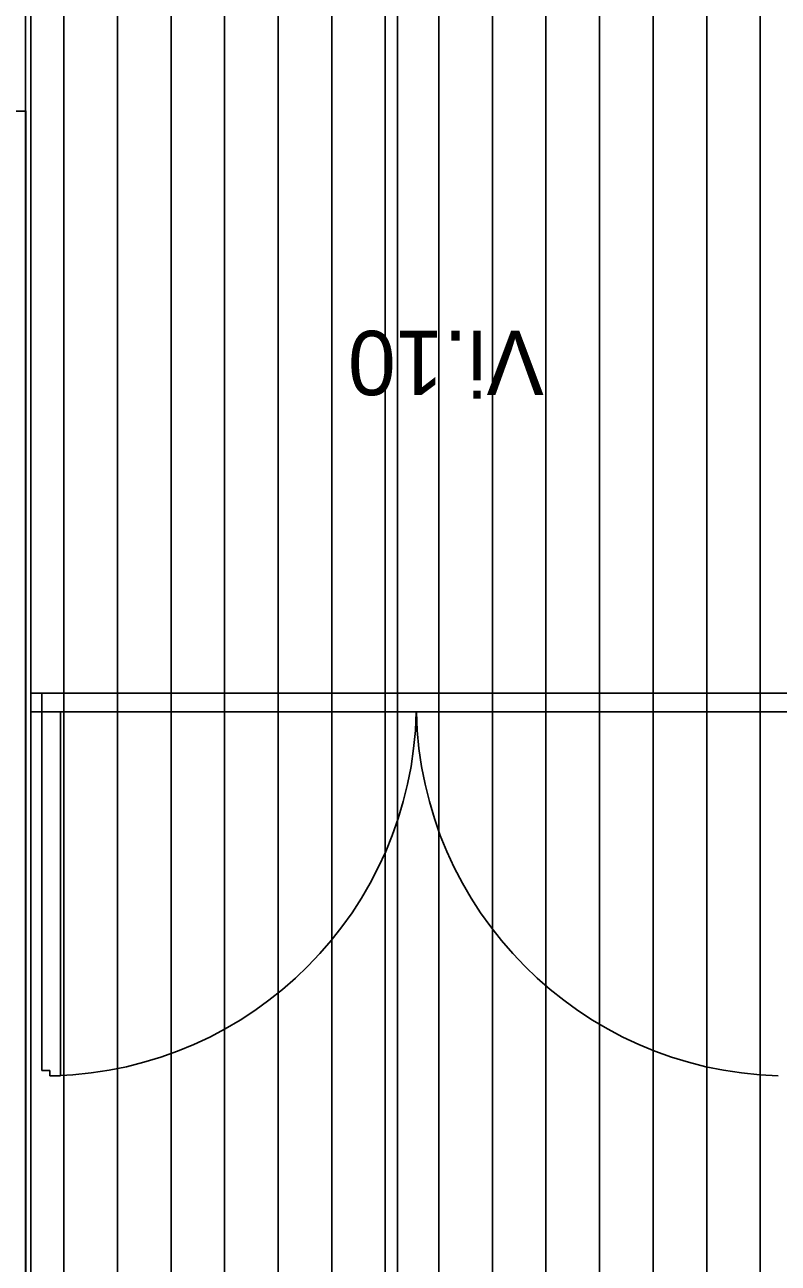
# Model space of a CAD drawing. Extents: x 1278 to 1356, y -253.7 to -224.
# Drawn here: x 1303.561 to 1304.967, y -239.071 to -236.76 of the extents above; entities that cross this region are included whole.
import ezdxf

# ---------------------------------------------------------------- set-up
doc = ezdxf.new("R2010")
doc.units = 0
for name, color, linetype in [('Level 10', 7, 'Continuous'), ('Level 13', 7, 'Continuous'), ('Level 4', 7, 'Continuous'), ('Level 40', 7, 'Continuous'), ('Level 65', 7, 'Continuous'), ('Level 66', 7, 'Continuous'), ('Level 67', 7, 'Continuous'), ('Level 93', 7, 'Continuous')]:
    doc.layers.add(name, color=color, linetype=linetype)

msp = doc.modelspace()

# ---------------------------------------------------------------- linework, layer by layer
at = {"layer": 'Level 10'}
for p, q in [((1303.6337, -243.574), (1303.6337, -235.1552)), ((1303.7337, -243.574), (1303.7337, -235.1552)), ((1303.8337, -243.574), (1303.8337, -235.1552)), ((1303.9337, -243.574), (1303.9337, -235.1552)), ((1304.0337, -243.574), (1304.0337, -235.1552)), ((1304.1337, -243.574), (1304.1337, -235.1552)), ((1304.2337, -243.574), (1304.2337, -235.1552)), ((1304.3337, -243.574), (1304.3337, -235.1552)), ((1304.4337, -243.574), (1304.4337, -235.1552)), ((1304.5337, -243.574), (1304.5337, -235.1552)), ((1304.6337, -243.574), (1304.6337, -235.1552)), ((1304.7337, -243.574), (1304.7337, -235.1552)), ((1304.8337, -243.574), (1304.8337, -235.1552)), ((1304.9337, -243.574), (1304.9337, -235.1552))]:
    msp.add_line(p, q, dxfattribs=at)
at = {"layer": 'Level 13'}
for p, q in [((1303.5923, -238.0075), (1303.5723, -238.0075)), ((1303.5923, -238.0075), (1303.5723, -238.0075)), ((1303.5923, -238.0075), (1303.5723, -238.0075)), ((1303.5923, -238.0425), (1303.5923, -238.0075)), ((1303.5923, -238.0425), (1303.5923, -238.0075)), ((1303.5923, -238.0425), (1303.5923, -238.0075)), ((1303.5923, -238.0425), (1303.5723, -238.0425)), ((1303.5923, -238.0425), (1303.5723, -238.0425)), ((1303.5923, -238.0425), (1303.5723, -238.0425)), ((1303.5923, -238.0425), (1303.5923, -238.7116)), ((1303.5923, -238.0425), (1303.5923, -238.7116)), ((1303.5923, -238.0425), (1303.5923, -238.7116)), ((1303.6273, -238.0425), (1303.5923, -238.0425)), ((1303.6273, -238.0425), (1303.5923, -238.0425)), ((1303.6273, -238.0425), (1303.5923, -238.0425)), ((1303.6273, -238.0425), (1303.6273, -238.7216)), ((1303.6273, -238.0425), (1303.6273, -238.7216)), ((1303.6273, -238.0425), (1303.6273, -238.7216)), ((1303.6073, -238.7116), (1303.5923, -238.7116)), ((1303.6073, -238.7116), (1303.5923, -238.7116)), ((1303.6073, -238.7116), (1303.5923, -238.7116)), ((1303.6073, -238.7116), (1303.6073, -238.7216)), ((1303.6073, -238.7116), (1303.6073, -238.7216)), ((1303.6073, -238.7116), (1303.6073, -238.7216)), ((1303.6273, -238.7216), (1303.6073, -238.7216)), ((1303.6273, -238.7216), (1303.6073, -238.7216)), ((1303.6273, -238.7216), (1303.6073, -238.7216))]:
    msp.add_line(p, q, dxfattribs=at)
at = {"layer": 'Level 4'}
for p, q in [((1305.0023, -238.0075), (1303.581, -238.0075)), ((1305.0023, -238.0425), (1303.616, -238.0425))]:
    msp.add_line(p, q, dxfattribs=at)
for centre, start, end in [((1303.5963, -238.0263), 271.6204, 358.6698), ((1304.987, -238.0263), 181.3302, 268.3796)]:
    msp.add_arc(centre, 0.6955, start, end, dxfattribs=at)
at = {"layer": 'Level 65'}
msp.add_line((1303.5723, -243.574), (1303.5723, -235.1552), dxfattribs=at)
at = {"layer": 'Level 66'}
msp.add_line((1303.5623, -243.584), (1303.5623, -232.264), dxfattribs=at)
msp.add_line((1303.5623, -243.584), (1303.5623, -232.264), dxfattribs=at)
msp.add_line((1303.5623, -243.584), (1303.5623, -232.264), dxfattribs=at)
at = {"layer": 'Level 67'}
msp.add_lwpolyline([(1303.4527, -242.8713), (1303.5627, -242.8713), (1303.5627, -236.9213), (1303.4527, -236.9213)], close=True, dxfattribs=at)
at = {"layer": 'Level 93'}
msp.add_line((1304.2565, -246.757), (1304.2565, -236.1407), dxfattribs=at)

# ---------------------------------------------------------------- texts
at = {"layer": 'Level 40'}
msp.add_text('Vi.10', height=0.12, rotation=180, dxfattribs=at).set_placement((1304.5298, -237.3313))

doc.saveas('drawing.dxf')
